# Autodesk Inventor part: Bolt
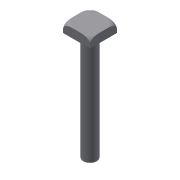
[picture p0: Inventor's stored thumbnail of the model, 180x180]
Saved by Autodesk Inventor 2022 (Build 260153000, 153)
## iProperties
Created: 2009-04
Part Number: Bolt
Document SubType Name: Modeling
Designer: Sham
Density: 1 g/cm^3
Material: Generic
Appearance: Default
Mass: 15.4123 g
Surface Area: 54.8695 cm^2
Volume: 15.4123 cm^3
Author: Sham
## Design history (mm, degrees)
sketch "Sketch1"
  geometry: L1 (-12, 12)-(12, 12); L2 (12, 12)-(12, -12); L3 (12, -12)-(-12, -12); L4 (-12, -12)-(-12, 12); 1 further point
  constraints: 8 end point, 2 parallel, 2 perpendicular, 1 horizontal, 1 other
  dimensions: "d0" = 24 distance of L1.start L1.end; "d1" = 12 distance from line of L2 point (0, 0); "d2" = 12 distance from line of L1 point (0, 0)
extrude "Extrusion1" new body sketch "Sketch1" distance "d3" = 8; taper "d4" = 0 deg
sketch "Sketch2"
  geometry: C1 r 6 at (0, 0)
  constraints: 1 centre point
  dimensions: "d5" = 12 diameter of C1
extrude "Extrusion2" join sketch "Sketch2" distance "d6" = 96; taper "d7" = 0 deg
workpoint "Work Point1"
workplane "Work Plane1"
sketch "Sketch3"
  geometry: L1 (33.941, 5)-(33.941, 6); L2 (28.941, 0)-(28.405, 0); L3 (16.971, 125.007)-(16.971, -22.043) reference; A1 r 5 centre (28.941, 5) between (28.941, 0) and (33.941, 5); 1 further point
  constraints: 4 end point, 2 point on circle, 2 point on line, 2 tangent, 1 centre point, 1 perpendicular
  dimensions: "d10" = 5 radius of A1
revolve "Revolution1" sketch "Sketch3" stored, may be unused: angle "d12" = 90 deg
body "Solid1"
other parameters: "d11" = 90 deg
